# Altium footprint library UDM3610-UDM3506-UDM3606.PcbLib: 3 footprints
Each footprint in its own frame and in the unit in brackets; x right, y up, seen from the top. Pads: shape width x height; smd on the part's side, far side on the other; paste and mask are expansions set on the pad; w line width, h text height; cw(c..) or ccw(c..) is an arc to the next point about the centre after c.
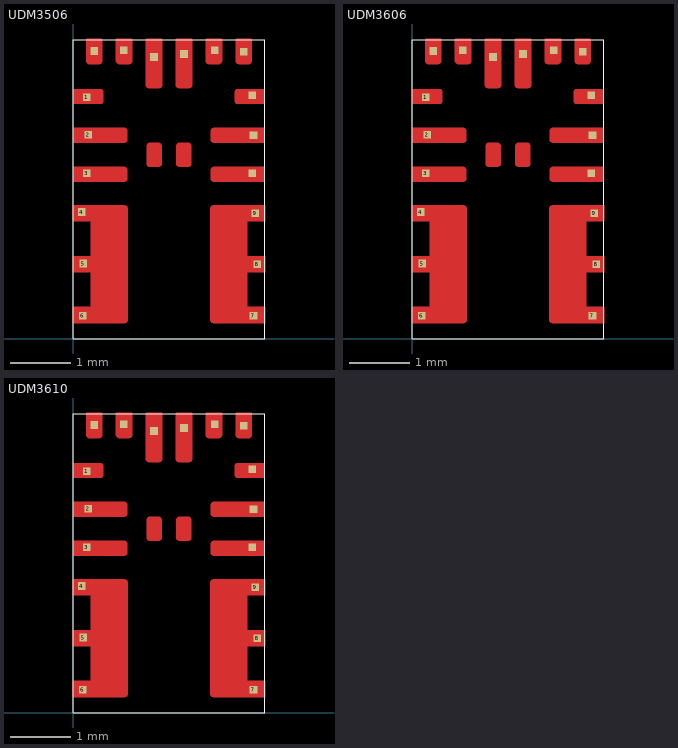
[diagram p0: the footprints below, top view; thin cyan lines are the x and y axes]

## UDM3506 [mil]
pads (18):
  rect 5x5 smd mask+0: 1(8.82,159.06) 2(9.84,134.25) 3(8.82,109.06) 4(5.66,83.46) 5(6.69,49.61) 6(6.3,15.35) 7(118.5,15.35) 8(120.87,49.2) 9(119.69,82.67) 10(117.72,109.06) 11(118.5,133.85) 12(117.72,160.24) 13(112.16,188.98) 14(92.91,189.76) 15(72.79,187.4) 16(53.11,185.43) 17(33.07,189.76) 18(13.78,189.37)
Top Layer:
  region: 8.41,183.06 8.41,196.84 8.41,196.92 8.47,197.07 8.58,197.19 8.73,197.25 8.82,197.25 18.66,197.25 18.74,197.25 18.89,197.19 19,197.07 19.07,196.92 19.07,196.84 19.07,183.06 19.07,182.59 18.71,181.71 18.04,181.04 17.16,180.68 16.69,180.68 10.78,180.68 10.31,180.68 9.44,181.04 8.77,181.71 8.41,182.59
  region: 28.09,183.06 28.09,196.84 28.09,196.92 28.15,197.07 28.27,197.19 28.42,197.25 28.5,197.25 38.34,197.25 38.42,197.25 38.58,197.19 38.69,197.07 38.75,196.92 38.75,196.84 38.75,183.06 38.75,182.59 38.39,181.71 37.72,181.04 36.85,180.68 36.38,180.68 30.47,180.68 30,180.68 29.12,181.04 28.45,181.71 28.09,182.59
  region: 47.78,167.31 47.78,166.84 48.14,165.96 48.81,165.3 49.68,164.93 50.15,164.93 56.06,164.93 56.53,164.93 57.4,165.29 58.07,165.96 58.44,166.83 58.44,167.3 58.44,167.31 58.44,196.84 58.44,196.92 58.38,197.07 58.26,197.19 58.11,197.25 58.03,197.25 48.19,197.25 48.1,197.25 47.95,197.19 47.84,197.07 47.78,196.92 47.78,196.84
  region: 67.46,167.31 67.46,196.84 67.46,196.92 67.52,197.07 67.64,197.19 67.79,197.25 67.87,197.25 77.71,197.25 77.79,197.25 77.95,197.19 78.06,197.07 78.12,196.92 78.12,196.84 78.12,167.31 78.12,166.84 77.76,165.96 77.09,165.3 76.22,164.93 75.75,164.93 69.84,164.93 69.37,164.93 68.49,165.3 67.82,165.96 67.46,166.84
  region: 87.15,183.06 87.15,196.84 87.15,196.92 87.21,197.07 87.32,197.19 87.47,197.25 87.56,197.25 97.4,197.25 97.48,197.25 97.63,197.19 97.75,197.07 97.81,196.92 97.81,196.84 97.81,183.06 97.81,182.59 97.45,181.71 96.78,181.04 95.9,180.68 95.43,180.68 89.52,180.68 89.05,180.68 88.18,181.04 87.51,181.71 87.15,182.59
  region: 106.83,183.06 106.83,196.84 106.83,196.92 106.89,197.07 107.01,197.19 107.16,197.25 107.24,197.25 117.08,197.25 117.16,197.25 117.32,197.19 117.43,197.07 117.49,196.92 117.49,196.84 117.49,183.06 117.49,182.59 117.13,181.71 116.46,181.04 115.59,180.68 115.12,180.68 109.21,180.68 108.74,180.68 107.86,181.04 107.19,181.71 106.83,182.59
  region: -0.04,154.52 17.67,154.52 18.07,154.52 18.79,154.82 19.34,155.37 19.64,156.09 19.64,156.48 19.64,162.39 19.64,162.78 19.34,163.5 18.79,164.06 18.07,164.36 17.67,164.36 -0.04,164.36
  region: 106.26,156.48 106.26,156.09 106.56,155.37 107.11,154.82 107.83,154.52 108.23,154.52 125.94,154.52 125.94,164.36 108.23,164.36 107.83,164.36 107.11,164.06 106.56,163.5 106.26,162.78 106.26,162.39
  region: -0.04,128.93 -0.04,138.77 33.42,138.77 33.81,138.77 34.54,138.47 35.09,137.91 35.39,137.19 35.39,136.8 35.39,130.89 35.39,130.5 35.09,129.78 34.54,129.22 33.81,128.93 33.42,128.93
  region: 90.51,130.89 90.51,130.5 90.81,129.78 91.36,129.22 92.09,128.93 92.48,128.93 125.94,128.93 125.94,138.77 92.48,138.77 92.09,138.77 91.36,138.47 90.81,137.91 90.51,137.19 90.51,136.8
  region: -0.04,103.33 33.42,103.33 33.81,103.33 34.54,103.63 35.09,104.19 35.39,104.91 35.39,105.3 35.39,111.21 35.39,111.6 35.09,112.32 34.54,112.88 33.81,113.18 33.42,113.18 -0.04,113.18
  region: 48.19,115.15 48.19,114.75 48.49,114.03 49.04,113.48 49.76,113.18 50.15,113.18 56.06,113.18 56.45,113.18 57.18,113.48 57.73,114.03 58.03,114.75 58.03,115.15 58.03,126.96 58.03,127.35 57.73,128.07 57.18,128.63 56.45,128.93 56.06,128.93 50.15,128.93 49.76,128.93 49.04,128.63 48.49,128.07 48.19,127.35 48.19,126.96
  region: 67.87,115.15 67.87,114.75 68.17,114.03 68.72,113.48 69.45,113.18 69.84,113.18 75.75,113.18 76.14,113.18 76.86,113.48 77.41,114.03 77.71,114.75 77.71,115.15 77.71,126.96 77.71,127.35 77.41,128.07 76.86,128.63 76.14,128.93 75.75,128.93 69.84,128.93 69.45,128.93 68.72,128.63 68.17,128.07 67.87,127.35 67.87,126.96
  region: 90.51,105.3 90.51,104.91 90.81,104.19 91.36,103.63 92.09,103.33 92.48,103.33 125.94,103.33 125.94,113.18 92.48,113.18 92.09,113.18 91.36,112.88 90.81,112.32 90.51,111.6 90.51,111.21
  region: -0.45,10.82 -0.45,20.66 -0.45,20.74 -0.39,20.89 -0.27,21 -0.12,21.07 -0.04,21.07 11.36,21.07 11.36,43.87 -0.04,43.87 -0.12,43.87 -0.27,43.93 -0.39,44.05 -0.45,44.2 -0.45,44.28 -0.45,54.12 -0.45,54.2 -0.39,54.35 -0.27,54.47 -0.12,54.53 -0.04,54.53 11.36,54.53 11.36,77.34 -0.04,77.34 -0.12,77.34 -0.27,77.4 -0.39,77.51 -0.45,77.66 -0.45,77.74 -0.45,87.59 -0.45,87.67 -0.39,87.82 -0.27,87.93 -0.12,88 -0.04,88 33.42,88 33.9,88 34.77,87.63 35.44,86.96 35.8,86.09 35.8,85.62 35.8,12.78 35.8,12.31 35.44,11.44 34.77,10.77 33.9,10.41 33.42,10.41 -0.04,10.41 -0.12,10.41 -0.27,10.47 -0.39,10.58 -0.45,10.73
  region: 90.1,12.78 90.1,12.31 90.46,11.44 91.13,10.77 92,10.41 92.48,10.41 125.94,10.41 126.02,10.41 126.17,10.47 126.29,10.58 126.35,10.73 126.35,10.82 126.35,20.66 126.35,20.74 126.29,20.89 126.17,21 126.02,21.07 125.94,21.07 114.54,21.07 114.54,43.87 125.94,43.87 126.02,43.87 126.17,43.93 126.29,44.05 126.35,44.2 126.35,44.28 126.35,54.12 126.35,54.2 126.29,54.35 126.17,54.47 126.02,54.53 125.94,54.53 114.54,54.53 114.54,77.34 125.94,77.34 126.02,77.34 126.17,77.4 126.29,77.51 126.35,77.66 126.35,77.74 126.35,87.59 126.35,87.67 126.29,87.82 126.17,87.93 126.02,88 125.94,88 92.48,88 92,88 91.13,87.63 90.46,86.96 90.1,86.09 90.1,85.62
Top Overlay:
  lines w0.79: -0.04,-0.01 125.94,-0.01 125.94,196.84 -0.04,196.84 -0.04,-0.01
Top Paste:
  drawing of 16 lines, arcs and shapes, not listed
Top Solder:
  drawing of 16 lines, arcs and shapes, not listed
3D body "UDM3506.STEP": height 87.09, standoff 0, extent 0,0 125.98,196.85

## UDM3606 [mil]
pads (18):
  rect 5x5 smd mask+0: 1(8.82,159.06) 2(9.84,134.25) 3(8.82,109.06) 4(5.66,83.46) 5(6.69,49.61) 6(6.3,15.35) 7(118.5,15.35) 8(120.87,49.2) 9(119.69,82.67) 10(117.72,109.06) 11(118.5,133.85) 12(117.72,160.24) 13(112.16,188.98) 14(92.91,189.76) 15(72.79,187.4) 16(53.11,185.43) 17(33.07,189.76) 18(13.78,189.37)
Top Layer:
  region: 90.1,12.78 90.1,12.31 90.46,11.44 91.13,10.77 92,10.41 92.48,10.41 125.94,10.41 126.02,10.41 126.17,10.47 126.29,10.58 126.35,10.73 126.35,10.82 126.35,20.66 126.35,20.74 126.29,20.89 126.17,21 126.02,21.07 125.94,21.07 114.54,21.07 114.54,43.87 125.94,43.87 126.02,43.87 126.17,43.93 126.29,44.05 126.35,44.2 126.35,44.28 126.35,54.12 126.35,54.2 126.29,54.35 126.17,54.47 126.02,54.53 125.94,54.53 114.54,54.53 114.54,77.34 125.94,77.34 126.02,77.34 126.17,77.4 126.29,77.51 126.35,77.66 126.35,77.74 126.35,87.59 126.35,87.67 126.29,87.82 126.17,87.93 126.02,88 125.94,88 92.48,88 92,88 91.13,87.63 90.46,86.96 90.1,86.09 90.1,85.62
  region: -0.45,10.82 -0.45,20.66 -0.45,20.74 -0.39,20.89 -0.27,21 -0.12,21.07 -0.04,21.07 11.36,21.07 11.36,43.87 -0.04,43.87 -0.12,43.87 -0.27,43.93 -0.39,44.05 -0.45,44.2 -0.45,44.28 -0.45,54.12 -0.45,54.2 -0.39,54.35 -0.27,54.47 -0.12,54.53 -0.04,54.53 11.36,54.53 11.36,77.34 -0.04,77.34 -0.12,77.34 -0.27,77.4 -0.39,77.51 -0.45,77.66 -0.45,77.74 -0.45,87.59 -0.45,87.67 -0.39,87.82 -0.27,87.93 -0.12,88 -0.04,88 33.42,88 33.9,88 34.77,87.63 35.44,86.96 35.8,86.09 35.8,85.62 35.8,12.78 35.8,12.31 35.44,11.44 34.77,10.77 33.9,10.41 33.42,10.41 -0.04,10.41 -0.12,10.41 -0.27,10.47 -0.39,10.58 -0.45,10.73
  region: 90.51,105.3 90.51,104.91 90.81,104.19 91.36,103.63 92.09,103.33 92.48,103.33 125.94,103.33 125.94,113.18 92.48,113.18 92.09,113.18 91.36,112.88 90.81,112.32 90.51,111.6 90.51,111.21
  region: 67.87,115.15 67.87,114.75 68.17,114.03 68.72,113.48 69.45,113.18 69.84,113.18 75.75,113.18 76.14,113.18 76.86,113.48 77.41,114.03 77.71,114.75 77.71,115.15 77.71,126.96 77.71,127.35 77.41,128.07 76.86,128.63 76.14,128.93 75.75,128.93 69.84,128.93 69.45,128.93 68.72,128.63 68.17,128.07 67.87,127.35 67.87,126.96
  region: 48.19,115.15 48.19,114.75 48.49,114.03 49.04,113.48 49.76,113.18 50.15,113.18 56.06,113.18 56.45,113.18 57.18,113.48 57.73,114.03 58.03,114.75 58.03,115.15 58.03,126.96 58.03,127.35 57.73,128.07 57.18,128.63 56.45,128.93 56.06,128.93 50.15,128.93 49.76,128.93 49.04,128.63 48.49,128.07 48.19,127.35 48.19,126.96
  region: -0.04,103.33 33.42,103.33 33.81,103.33 34.54,103.63 35.09,104.19 35.39,104.91 35.39,105.3 35.39,111.21 35.39,111.6 35.09,112.32 34.54,112.88 33.81,113.18 33.42,113.18 -0.04,113.18
  region: 90.51,130.89 90.51,130.5 90.81,129.78 91.36,129.22 92.09,128.93 92.48,128.93 125.94,128.93 125.94,138.77 92.48,138.77 92.09,138.77 91.36,138.47 90.81,137.91 90.51,137.19 90.51,136.8
  region: -0.04,128.93 -0.04,138.77 33.42,138.77 33.81,138.77 34.54,138.47 35.09,137.91 35.39,137.19 35.39,136.8 35.39,130.89 35.39,130.5 35.09,129.78 34.54,129.22 33.81,128.93 33.42,128.93
  region: 106.26,156.48 106.26,156.09 106.56,155.37 107.11,154.82 107.83,154.52 108.23,154.52 125.94,154.52 125.94,164.36 108.23,164.36 107.83,164.36 107.11,164.06 106.56,163.5 106.26,162.78 106.26,162.39
  region: -0.04,154.52 17.67,154.52 18.07,154.52 18.79,154.82 19.34,155.37 19.64,156.09 19.64,156.48 19.64,162.39 19.64,162.78 19.34,163.5 18.79,164.06 18.07,164.36 17.67,164.36 -0.04,164.36
  region: 106.83,183.06 106.83,196.84 106.83,196.92 106.89,197.07 107.01,197.19 107.16,197.25 107.24,197.25 117.08,197.25 117.16,197.25 117.32,197.19 117.43,197.07 117.49,196.92 117.49,196.84 117.49,183.06 117.49,182.59 117.13,181.71 116.46,181.04 115.59,180.68 115.12,180.68 109.21,180.68 108.74,180.68 107.86,181.04 107.19,181.71 106.83,182.59
  region: 87.15,183.06 87.15,196.84 87.15,196.92 87.21,197.07 87.32,197.19 87.47,197.25 87.56,197.25 97.4,197.25 97.48,197.25 97.63,197.19 97.75,197.07 97.81,196.92 97.81,196.84 97.81,183.06 97.81,182.59 97.45,181.71 96.78,181.04 95.9,180.68 95.43,180.68 89.52,180.68 89.05,180.68 88.18,181.04 87.51,181.71 87.15,182.59
  region: 67.46,167.31 67.46,196.84 67.46,196.92 67.52,197.07 67.64,197.19 67.79,197.25 67.87,197.25 77.71,197.25 77.79,197.25 77.95,197.19 78.06,197.07 78.12,196.92 78.12,196.84 78.12,167.31 78.12,166.84 77.76,165.96 77.09,165.3 76.22,164.93 75.75,164.93 69.84,164.93 69.37,164.93 68.49,165.3 67.82,165.96 67.46,166.84
  region: 47.78,167.31 47.78,166.84 48.14,165.96 48.81,165.3 49.68,164.93 50.15,164.93 56.06,164.93 56.53,164.93 57.4,165.29 58.07,165.96 58.44,166.83 58.44,167.3 58.44,167.31 58.44,196.84 58.44,196.92 58.38,197.07 58.26,197.19 58.11,197.25 58.03,197.25 48.19,197.25 48.1,197.25 47.95,197.19 47.84,197.07 47.78,196.92 47.78,196.84
  region: 28.09,183.06 28.09,196.84 28.09,196.92 28.15,197.07 28.27,197.19 28.42,197.25 28.5,197.25 38.34,197.25 38.42,197.25 38.58,197.19 38.69,197.07 38.75,196.92 38.75,196.84 38.75,183.06 38.75,182.59 38.39,181.71 37.72,181.04 36.85,180.68 36.38,180.68 30.47,180.68 30,180.68 29.12,181.04 28.45,181.71 28.09,182.59
  region: 8.41,183.06 8.41,196.84 8.41,196.92 8.47,197.07 8.58,197.19 8.73,197.25 8.82,197.25 18.66,197.25 18.74,197.25 18.89,197.19 19,197.07 19.07,196.92 19.07,196.84 19.07,183.06 19.07,182.59 18.71,181.71 18.04,181.04 17.16,180.68 16.69,180.68 10.78,180.68 10.31,180.68 9.44,181.04 8.77,181.71 8.41,182.59
Top Overlay:
  lines w0.79: -0.04,-0.01 -0.04,196.84 125.94,196.84 125.94,-0.01 -0.04,-0.01
Top Paste:
  drawing of 16 lines, arcs and shapes, not listed
Top Solder:
  drawing of 16 lines, arcs and shapes, not listed
3D body "UDM3606.STEP": height 87.09, standoff 0, extent 0,0 125.98,196.85

## UDM3610 [mil]
pads (18):
  rect 5x5 smd mask+0: 1(8.82,159.06) 2(9.84,134.25) 3(8.82,109.06) 4(5.66,83.46) 5(6.69,49.61) 6(6.3,15.35) 7(118.5,15.35) 8(120.87,49.2) 9(119.69,82.67) 10(117.72,109.06) 11(118.5,133.85) 12(117.72,160.24) 13(112.16,188.98) 14(92.91,189.76) 15(72.79,187.4) 16(53.11,185.43) 17(33.07,189.76) 18(13.78,189.37)
Top Layer:
  region: 90.1,12.78 90.1,12.31 90.46,11.44 91.13,10.77 92,10.41 92.48,10.41 125.94,10.41 126.02,10.41 126.17,10.47 126.29,10.58 126.35,10.73 126.35,10.82 126.35,20.66 126.35,20.74 126.29,20.89 126.17,21 126.02,21.07 125.94,21.07 114.54,21.07 114.54,43.87 125.94,43.87 126.02,43.87 126.17,43.93 126.29,44.05 126.35,44.2 126.35,44.28 126.35,54.12 126.35,54.2 126.29,54.35 126.17,54.47 126.02,54.53 125.94,54.53 114.54,54.53 114.54,77.34 125.94,77.34 126.02,77.34 126.17,77.4 126.29,77.51 126.35,77.66 126.35,77.74 126.35,87.59 126.35,87.67 126.29,87.82 126.17,87.93 126.02,88 125.94,88 92.48,88 92,88 91.13,87.63 90.46,86.96 90.1,86.09 90.1,85.62
  region: -0.45,10.82 -0.45,20.66 -0.45,20.74 -0.39,20.89 -0.27,21 -0.12,21.07 -0.04,21.07 11.36,21.07 11.36,43.87 -0.04,43.87 -0.12,43.87 -0.27,43.93 -0.39,44.05 -0.45,44.2 -0.45,44.28 -0.45,54.12 -0.45,54.2 -0.39,54.35 -0.27,54.47 -0.12,54.53 -0.04,54.53 11.36,54.53 11.36,77.34 -0.04,77.34 -0.12,77.34 -0.27,77.4 -0.39,77.51 -0.45,77.66 -0.45,77.74 -0.45,87.59 -0.45,87.67 -0.39,87.82 -0.27,87.93 -0.12,88 -0.04,88 33.42,88 33.9,88 34.77,87.63 35.44,86.96 35.8,86.09 35.8,85.62 35.8,12.78 35.8,12.31 35.44,11.44 34.77,10.77 33.9,10.41 33.42,10.41 -0.04,10.41 -0.12,10.41 -0.27,10.47 -0.39,10.58 -0.45,10.73
  region: 90.51,105.3 90.51,104.91 90.81,104.19 91.36,103.63 92.09,103.33 92.48,103.33 125.94,103.33 125.94,113.18 92.48,113.18 92.09,113.18 91.36,112.88 90.81,112.32 90.51,111.6 90.51,111.21
  region: 67.87,115.15 67.87,114.75 68.17,114.03 68.72,113.48 69.45,113.18 69.84,113.18 75.75,113.18 76.14,113.18 76.86,113.48 77.41,114.03 77.71,114.75 77.71,115.15 77.71,126.96 77.71,127.35 77.41,128.07 76.86,128.63 76.14,128.93 75.75,128.93 69.84,128.93 69.45,128.93 68.72,128.63 68.17,128.07 67.87,127.35 67.87,126.96
  region: 48.19,115.15 48.19,114.75 48.49,114.03 49.04,113.48 49.76,113.18 50.15,113.18 56.06,113.18 56.45,113.18 57.18,113.48 57.73,114.03 58.03,114.75 58.03,115.15 58.03,126.96 58.03,127.35 57.73,128.07 57.18,128.63 56.45,128.93 56.06,128.93 50.15,128.93 49.76,128.93 49.04,128.63 48.49,128.07 48.19,127.35 48.19,126.96
  region: -0.04,103.33 33.42,103.33 33.81,103.33 34.54,103.63 35.09,104.19 35.39,104.91 35.39,105.3 35.39,111.21 35.39,111.6 35.09,112.32 34.54,112.88 33.81,113.18 33.42,113.18 -0.04,113.18
  region: 90.51,130.89 90.51,130.5 90.81,129.78 91.36,129.22 92.09,128.93 92.48,128.93 125.94,128.93 125.94,138.77 92.48,138.77 92.09,138.77 91.36,138.47 90.81,137.91 90.51,137.19 90.51,136.8
  region: -0.04,128.93 -0.04,138.77 33.42,138.77 33.81,138.77 34.54,138.47 35.09,137.91 35.39,137.19 35.39,136.8 35.39,130.89 35.39,130.5 35.09,129.78 34.54,129.22 33.81,128.93 33.42,128.93
  region: 106.26,156.48 106.26,156.09 106.56,155.37 107.11,154.82 107.83,154.52 108.23,154.52 125.94,154.52 125.94,164.36 108.23,164.36 107.83,164.36 107.11,164.06 106.56,163.5 106.26,162.78 106.26,162.39
  region: -0.04,154.52 17.67,154.52 18.07,154.52 18.79,154.82 19.34,155.37 19.64,156.09 19.64,156.48 19.64,162.39 19.64,162.78 19.34,163.5 18.79,164.06 18.07,164.36 17.67,164.36 -0.04,164.36
  region: 106.83,183.06 106.83,196.84 106.83,196.92 106.89,197.07 107.01,197.19 107.16,197.25 107.24,197.25 117.08,197.25 117.16,197.25 117.32,197.19 117.43,197.07 117.49,196.92 117.49,196.84 117.49,183.06 117.49,182.59 117.13,181.71 116.46,181.04 115.59,180.68 115.12,180.68 109.21,180.68 108.74,180.68 107.86,181.04 107.19,181.71 106.83,182.59
  region: 87.15,183.06 87.15,196.84 87.15,196.92 87.21,197.07 87.32,197.19 87.47,197.25 87.56,197.25 97.4,197.25 97.48,197.25 97.63,197.19 97.75,197.07 97.81,196.92 97.81,196.84 97.81,183.06 97.81,182.59 97.45,181.71 96.78,181.04 95.9,180.68 95.43,180.68 89.52,180.68 89.05,180.68 88.18,181.04 87.51,181.71 87.15,182.59
  region: 67.46,167.31 67.46,196.84 67.46,196.92 67.52,197.07 67.64,197.19 67.79,197.25 67.87,197.25 77.71,197.25 77.79,197.25 77.95,197.19 78.06,197.07 78.12,196.92 78.12,196.84 78.12,167.31 78.12,166.84 77.76,165.96 77.09,165.3 76.22,164.93 75.75,164.93 69.84,164.93 69.37,164.93 68.49,165.3 67.82,165.96 67.46,166.84
  region: 47.78,167.31 47.78,166.84 48.14,165.96 48.81,165.3 49.68,164.93 50.15,164.93 56.06,164.93 56.53,164.93 57.4,165.29 58.07,165.96 58.44,166.83 58.44,167.3 58.44,167.31 58.44,196.84 58.44,196.92 58.38,197.07 58.26,197.19 58.11,197.25 58.03,197.25 48.19,197.25 48.1,197.25 47.95,197.19 47.84,197.07 47.78,196.92 47.78,196.84
  region: 28.09,183.06 28.09,196.84 28.09,196.92 28.15,197.07 28.27,197.19 28.42,197.25 28.5,197.25 38.34,197.25 38.42,197.25 38.58,197.19 38.69,197.07 38.75,196.92 38.75,196.84 38.75,183.06 38.75,182.59 38.39,181.71 37.72,181.04 36.85,180.68 36.38,180.68 30.47,180.68 30,180.68 29.12,181.04 28.45,181.71 28.09,182.59
  region: 8.41,183.06 8.41,196.84 8.41,196.92 8.47,197.07 8.58,197.19 8.73,197.25 8.82,197.25 18.66,197.25 18.74,197.25 18.89,197.19 19,197.07 19.07,196.92 19.07,196.84 19.07,183.06 19.07,182.59 18.71,181.71 18.04,181.04 17.16,180.68 16.69,180.68 10.78,180.68 10.31,180.68 9.44,181.04 8.77,181.71 8.41,182.59
Top Overlay:
  lines w0.79: -0.04,-0.01 -0.04,196.84 125.94,196.84 125.94,-0.01 -0.04,-0.01
Top Paste:
  drawing of 16 lines, arcs and shapes, not listed
Top Solder:
  drawing of 16 lines, arcs and shapes, not listed
3D body "UDM3610.STEP": height 87.09, standoff 0, extent 0.01,0 125.99,196.85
